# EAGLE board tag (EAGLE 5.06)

No outline drawn. Coordinates in mm, seen from the top.
Copper layers (1*16): Top 0.035mm / dielectric 1.5mm / Bottom 0.035mm
Design rules "default": minimum track width 10mil, minimum drill 24mil, track to track 8mil, track to pad 8mil, pad to pad 8mil, via to via 8mil, smd to smd 8mil, copper to edge 40mil, drill to drill 8mil, minimum pad ring 10mil, minimum via ring 8mil, stop-mask expansion 4mil, vias tented up to drill 0mil, thermal gap 10mil

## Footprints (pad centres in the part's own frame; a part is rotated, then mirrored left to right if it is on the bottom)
TC2030-MCP = smd 0.787 x 0.787: 1 1.27,-0.635; 2 1.27,0.635; 3 2.54,-0.635; 4 2.54,0.635; 5 3.81,-0.635; 6 3.81,0.635 | hole 0.95: 0,0; 5.08,-1.016; 5.08,1.016 | hole 2.375: 0,2.54; 0,-2.54; 3.175,-2.54; 3.175,2.54
TC2030-MCP-NL = smd 0.787 x 0.787: 1 1.27,-0.635; 2 1.27,0.635; 3 2.54,-0.635; 4 2.54,0.635; 5 3.81,-0.635; 6 3.81,0.635 | hole 0.95: 0,0; 5.08,-1.016; 5.08,1.016
TC2030-MCP-NL-CP = smd 0.787 x 0.787: 1 1.27,-0.635; 2 1.27,0.635; 3 2.54,-0.635; 4 2.54,0.635; 5 3.81,-0.635; 6 3.81,0.635 | hole 1.6: 0,0; 5.08,1.016; 5.08,-1.016

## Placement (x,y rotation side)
E$1  [TC2030-MCP]  0,0 0 top
E$2  [TC2030-MCP-NL]  12.7,0 0 top
E$3  [TC2030-MCP-NL-CP]  25.4,0 0 top

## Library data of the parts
E$1-E$3 = tag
